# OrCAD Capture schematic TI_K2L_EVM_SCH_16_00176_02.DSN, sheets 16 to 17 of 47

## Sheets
16 PAGE18 : K2L_SOC-AMC-4: size C; title: K2L LVDS SigMux, Clock Mux, K2L Reset, K2L CML Serdes JESD/AIL,
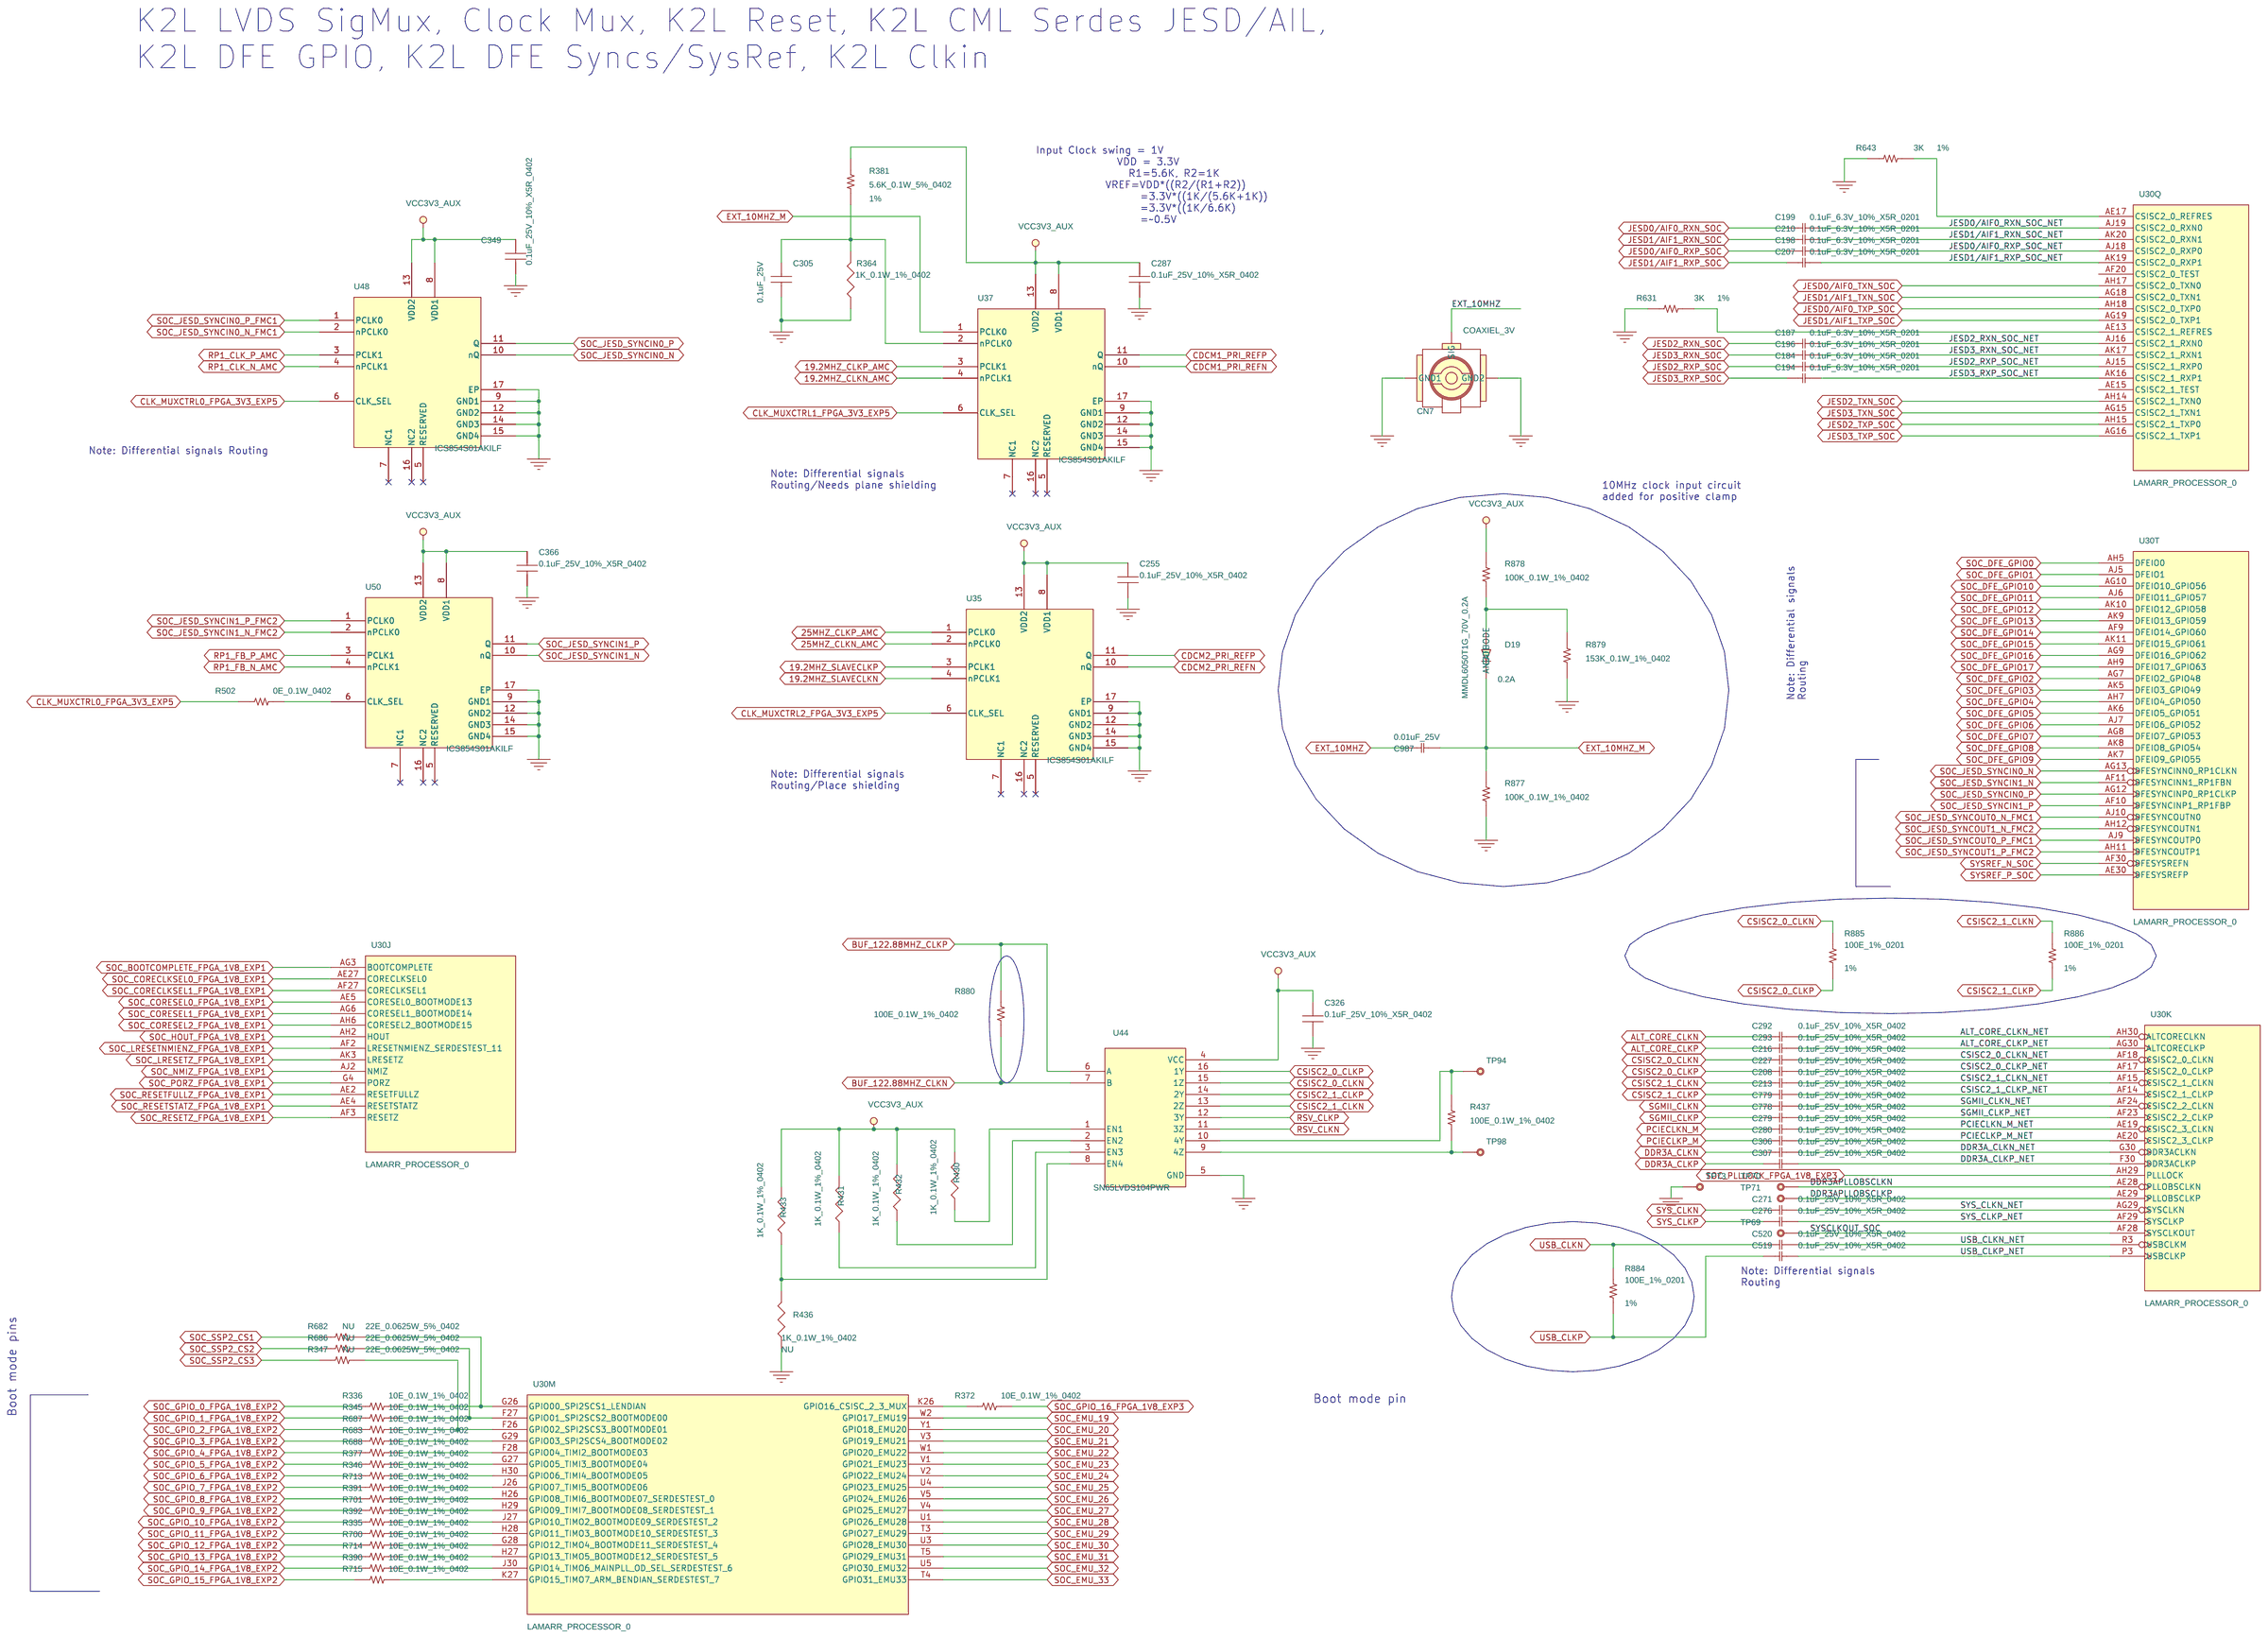
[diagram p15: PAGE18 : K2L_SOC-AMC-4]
17 PAGE47 : REVISION HISTORY: size C; title: REVISION HISTORY
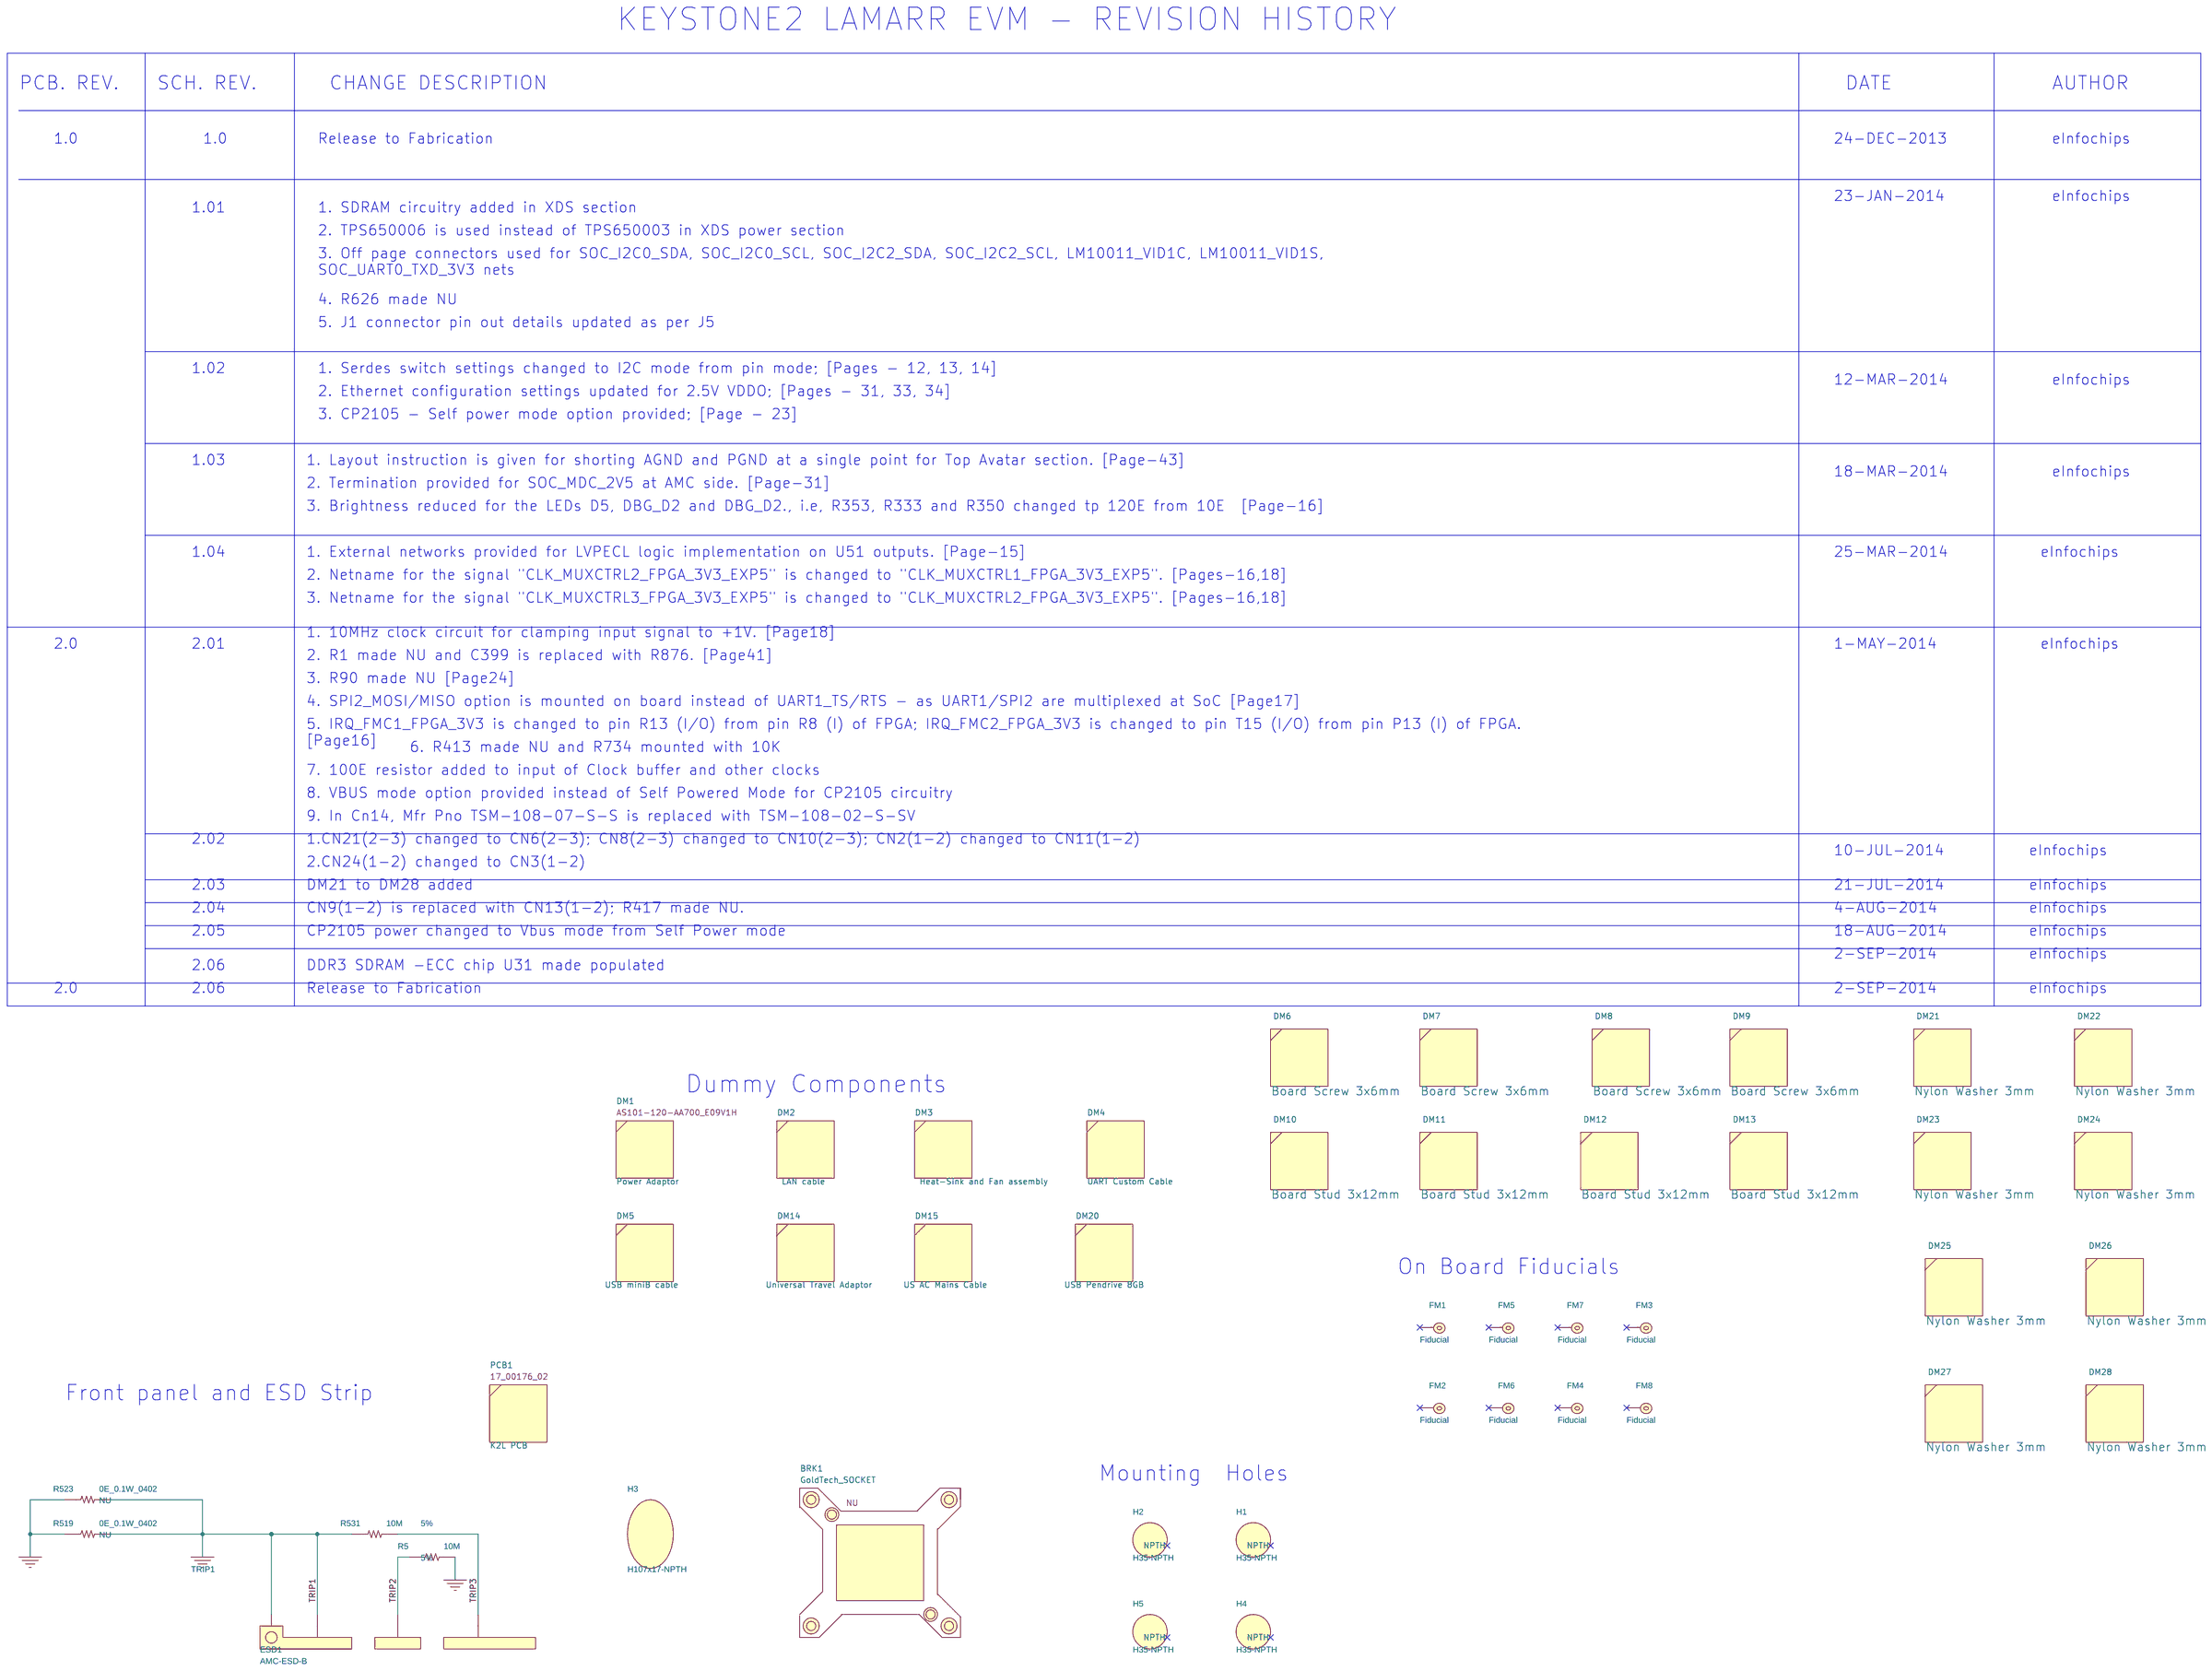
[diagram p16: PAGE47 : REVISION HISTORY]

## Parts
sheet PAGE18 : K2L_SOC-AMC-4
C184  0.1uF_6.3V_10%_X5R_0201  [CC0201]
C187  0.1uF_6.3V_10%_X5R_0201  [CC0201]
C194  0.1uF_6.3V_10%_X5R_0201  [CC0201]
C196  0.1uF_6.3V_10%_X5R_0201  [CC0201]
C198  0.1uF_6.3V_10%_X5R_0201  [CC0201]
C199  0.1uF_6.3V_10%_X5R_0201  [CC0201]
C207  0.1uF_6.3V_10%_X5R_0201  [CC0201]
C208  0.1uF_25V_10%_X5R_0402  [C0402]
C210  0.1uF_6.3V_10%_X5R_0201  [CC0201]
C213  0.1uF_25V_10%_X5R_0402  [C0402]
C216  0.1uF_25V_10%_X5R_0402  [C0402]
C227  0.1uF_25V_10%_X5R_0402  [C0402]
C255  0.1uF_25V_10%_X5R_0402  [C0402]
C271  0.1uF_25V_10%_X5R_0402  [C0402]
C276  0.1uF_25V_10%_X5R_0402  [C0402]
C279  0.1uF_25V_10%_X5R_0402  [C0402]
C280  0.1uF_25V_10%_X5R_0402  [C0402]
C287  0.1uF_25V_10%_X5R_0402  [C0402]
C292  0.1uF_25V_10%_X5R_0402  [C0402]
C293  0.1uF_25V_10%_X5R_0402  [C0402]
C305  0.1uF_25V  [C0402]
C306  0.1uF_25V_10%_X5R_0402  [C0402]
C307  0.1uF_25V_10%_X5R_0402  [C0402]
C326  0.1uF_25V_10%_X5R_0402  [C0402]
C349  0.1uF_25V_10%_X5R_0402  [C0402]
C366  0.1uF_25V_10%_X5R_0402  [C0402]
C519  0.1uF_25V_10%_X5R_0402  [C0402]
C520  0.1uF_25V_10%_X5R_0402  [C0402]
C778  0.1uF_25V_10%_X5R_0402  [C0402]
C779  0.1uF_25V_10%_X5R_0402  [C0402]
C987  0.01uF_25V  [C0402]
CN7  COAXIEL_3V  [HS_UFL-R-SMT-1]
D19  MMDL6050T1G_70V_0.2A  [SOD323]
R335  10E_0.1W_1%_0402  [R0402]
R336  10E_0.1W_1%_0402  [R0402]
R345  10E_0.1W_1%_0402  [R0402]
R346  10E_0.1W_1%_0402  [R0402]
R347  22E_0.0625W_5%_0402  [R0402]
R364  1K_0.1W_1%_0402  [R0402]
R372  10E_0.1W_1%_0402  [R0402]
R377  10E_0.1W_1%_0402  [R0402]
R381  5.6K_0.1W_5%_0402  [R0402]
R390  10E_0.1W_1%_0402  [R0402]
R391  10E_0.1W_1%_0402  [R0402]
R392  10E_0.1W_1%_0402  [R0402]
R430  1K_0.1W_1%_0402  [R0402]
R431  1K_0.1W_1%_0402  [R0402]
R432  1K_0.1W_1%_0402  [R0402]
R433  1K_0.1W_1%_0402  [R0402]
R436  1K_0.1W_1%_0402  [R0402]
R437  100E_0.1W_1%_0402  [R0402]
R502  0E_0.1W_0402  [R0402]
R631  3K  [RC0201_IPC7351_EINF]
R643  3K  [RC0201_IPC7351_EINF]
R682  22E_0.0625W_5%_0402  [R0402]
R683  10E_0.1W_1%_0402  [R0402]
R686  22E_0.0625W_5%_0402  [R0402]
R687  10E_0.1W_1%_0402  [R0402]
R688  10E_0.1W_1%_0402  [R0402]
R700  10E_0.1W_1%_0402  [R0402]
R701  10E_0.1W_1%_0402  [R0402]
R713  10E_0.1W_1%_0402  [R0402]
R714  10E_0.1W_1%_0402  [R0402]
R715  10E_0.1W_1%_0402  [R0402]
R877  100K_0.1W_1%_0402  [R0402]
R878  100K_0.1W_1%_0402  [R0402]
R879  153K_0.1W_1%_0402  [R0402]
R880  100E_0.1W_1%_0402  [R0402]
R884  100E_1%_0201  [RC0201_IPC7351_EINF]
R885  100E_1%_0201  [RC0201_IPC7351_EINF]
R886  100E_1%_0201  [RC0201_IPC7351_EINF]
TP69  TP  [TP-S40]
TP70  TP  [TP-S40]
TP71  TP  [TP-S40]
TP73  TP  [TP-S40]
TP94  TP  [TP-S40]
TP98  TP  [TP-S40]
U35  ICS854S01AKILF  [VFQFN50P300X300X100-17N_EINF]
U37  ICS854S01AKILF  [VFQFN50P300X300X100-17N_EINF]
U44  SN65LVDS104PWR  [TSSOP65P640_16]
U48  ICS854S01AKILF  [VFQFN50P300X300X100-17N_EINF]
U50  ICS854S01AKILF  [VFQFN50P300X300X100-17N_EINF]
sheet PAGE24 : K2L_JTAG
U30  LAMARR_PROCESSOR_0  [SKTBGA_Z3566_SS900-RHFB-BGA080]  (sections A,B,C,D,E,F,G,H,I,J,K,L,M,N,O,P,Q,R,S,T,U)
sheet PAGE47 : REVISION HISTORY
BRK1  GoldTech_SOCKET  [NA]
DM1  Power Adaptor  [NA]
DM2  LAN cable  [NA]
DM3  Heat-Sink and Fan assembly  [NA]
DM4  UART Custom Cable  [NA]
DM5  USB miniB cable  [NA]
DM6  Board Screw 3x6mm  [NA]
DM7  Board Screw 3x6mm  [NA]
DM8  Board Screw 3x6mm  [NA]
DM9  Board Screw 3x6mm  [NA]
DM10  Board Stud 3x12mm  [NA]
DM11  Board Stud 3x12mm  [NA]
DM12  Board Stud 3x12mm  [NA]
DM13  Board Stud 3x12mm  [NA]
DM14  Universal Travel Adaptor  [NA]
DM15  US AC Mains Cable  [NA]
DM20  USB Pendrive 8GB  [NA]
DM21  Nylon Washer 3mm  [NA]
DM22  Nylon Washer 3mm  [NA]
DM23  Nylon Washer 3mm  [NA]
DM24  Nylon Washer 3mm  [NA]
DM25  Nylon Washer 3mm  [NA]
DM26  Nylon Washer 3mm  [NA]
DM27  Nylon Washer 3mm  [NA]
DM28  Nylon Washer 3mm  [NA]
ESD1  AMC-ESD-B  [AMC-ESD-B]
FM1  Fiducial  [Fiducial]
FM2  Fiducial  [Fiducial]
FM3  Fiducial  [Fiducial]
FM4  Fiducial  [Fiducial]
FM5  Fiducial  [Fiducial]
FM6  Fiducial  [Fiducial]
FM7  Fiducial  [Fiducial]
FM8  Fiducial  [Fiducial]
H1  H35-NPTH  [H35-NPTH]
H2  H35-NPTH  [H35-NPTH]
H3  H107x17-NPTH  [H107x17-NPTH]
H4  H35-NPTH  [H35-NPTH]
H5  H35-NPTH  [H35-NPTH]
PCB1  K2L PCB  [NA]
R5  10M  [R1206]
R519  0E_0.1W_0402  [R0402]
R523  0E_0.1W_0402  [R0402]
R531  10M  [R1206]

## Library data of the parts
C184 C187 C194 C196 C198 C199 C207 C210 = 11_C_12: CAP CER 0.1UF 6.3V 10% X5R 0201; Alt Mfg: Taiyo Yuden; Alt Mfg Part#: TMK105BJ104KV-F; Characteristic: <Characteristic>; Distributor_name: DIGIKEY; Distributor_part_number: 445-1796-1-ND; EIC Part#: 03_00583_01; Manufacture: TDK Corporation; Manufacture Part Number: C0603X5R0J104K030BC; Manufacture(English): TDK Corporation; Manufacture_Part_Number: C0603X5R0J104K030BC; Manufacturer: TDK Corporation; Manufacturer_Part_No: C0603X5R0J104K030BC; Mfg: TDK Corporation; Mfg Part#: 03_00583_01; Mfr_name: TDK Corporation; Mfr_part_number: C0603X5R0J104K030BC; Oper. Temp. Range: -55°C ~ 85°C; Package: 0201; Price @ 1: 0.10000; Price @ 10K: 0.00675; Price @ 1K: 0.00810; ProcessType: SMT; RoHS: Yes; Tolerance: 10%; Vendor: DIGIKEY; Vendor Part#: 445-1796-2-ND; Vendor_Part_No: 445-1796-1-ND; Voltage: 6.3V; eI Part#: 03_00583_01
C208 C213 C216 C227 C271 C276 C279 C280 C292 C293 C306 C307 C519 C520 C778 C779 = 11_C_0: CAP CER 0.1UF 25V 10% X5R 0402; Distributor_name: DIGIKEY; Distributor_part_number: 445-4964-1-ND; EIC Part#: 03_00470_02; Manufacture: TDK Corporation; Manufacture Part Number: C1005X5R1E104K050BC; Manufacture(English): TDK Corporation; Manufacture_Part_Number: GRM155R71C104KA88D; Manufacturer: TDK Corporation; Manufacturer_Part_No: C1005X5R1E104K050BC; Mfg: Murata Electronics North America; Mfg Part#: 03_00470_02; Mfr_name: TDK Corporation; Mfr_part_number: C1005X5R1E104K050BC; Package: 0402; Price @ 1: 0.10000; Price @ 1K: 0.00420; ProcessType: SMT; Tolerance: 10%; Vendor: DIGIKEY; Vendor Part#: 445-4964-1-ND; Vendor_Part_No: 445-4964-1-ND; eI Part#: 03_00470_02
C255 C287 C305 C326 C349 C366 = CAP: CAP CER 0.1UF 25V 10% X5R 0402; Distributor_name: DIGIKEY; Distributor_part_number: 445-4964-1-ND; EIC Part#: 03_00470_02; Manufacture: TDK Corporation; Manufacture Part Number: C1005X5R1E104K050BC; Manufacture(English): TDK Corporation; Manufacture_Part_Number: GRM155R61E104KA87D; Manufacturer: TDK Corporation; Manufacturer_Part_No: C1005X5R1E104K050BC; Mfg: Murata Electronics North America; Mfg Part#: 03_00470_02; Mfr_name: TDK Corporation; Mfr_part_number: C1005X5R1E104K050BC; Price @ 1: 0.10000; Price @ 1K: 0.00960; RoHS Compliant?: RoHS Compliant; Vendor: DIGIKEY; Vendor Part#: 445-4964-1-ND; Vendor_Part_No: 445-4964-1-ND; eI Part#: 03_00470_02
C987 = 11_C_0: CAP CER 10000PF 25V 10% X7R 0402; Alt Mfg: Murata; Alt Mfg Part#: GRM155R71C103KA01D; Distributor_name: DIGIKEY; Distributor_part_number: 445-1260-1-ND; EIC Part#: 03_00029_04; Manufacture: TDK Corporation; Manufacture Part Number: C1005X7R1E103K; Manufacture(English): TDK Corporation; Manufacture_Part_Number: C1005X7R1E103K; Manufacturer: TDK Corporation; Manufacturer_Part_No: C1005X7R1E103K; Mfg: TDK Corporation; Mfg Part#: 03_00029_04; Mfr_name: TDK Corporation; Mfr_part_number: C1005X7R1E103K; Oper. Temp. Range: -55C to 125C; Package: 0402; Price @ 1: 0.10000; Price @ 10K: 0.00420; Price @ 1K: 0.00600; ProcessType: SMT; RoHS: Yes; Tolerance: 10%; Vendor: DIGIKEY; Vendor Part#: PCC103BQCT-ND; Vendor_Part_No: 445-1260-1-ND; Voltage: 16V; eI Part#: 03_00029_04
CN7 = 1654_HS_UFL-R-SMT-1_0: CONN UMC JACK STR 50 OHM SMD; Advansus_Part_Number: 12GA1654002618; Distributor_name: DIGIKEY; Distributor_part_number: H11891CT-ND; EIC Part#: TBD; Manufacture: Hirose Electric Co Ltd; Manufacture Part Number: U.FL-R-SMT-1(10); Manufacture(English): Hirose Electric Co Ltd; Manufacture_Part_Number: U.FL-R-SMT-1(10); Manufacturer: Hirose Electric Co Ltd; Manufacturer_Part_No: U.FL-R-SMT-1(10); Mfg: Hirose Electric Co Ltd; Mfg Part#: TBD; Mfr_name: Hirose Electric Co Ltd; Mfr_part_number: U.FL-R-SMT-1(10); Package: COAXIEL3P; Part_Number: 1654002618; Price @ 1: 1.67000; Price @ 10K: 0.58000; Price @ 1K: 0.70400; ProcessType: SMT; Vendor: DIGIKEY; Vendor_Part_No: H11891CT-ND; eI Part#: TBD
D19 = 130_SCHOTTKY_0805_3: DIODE SWITCHING 70V 0.2A SOD323; Characteristic: 0.2A; Distributor_name: DIGIKEY; Distributor_part_number: MMDL6050T1GOSCT-ND; EIC Part#: TBD; Manufacture: ON Semiconductor; Manufacture Part Number: MMDL6050T1G; Manufacture(English): ON Semiconductor; Manufacture_Part_Number: MMDL6050T1G; Manufacturer: ON Semiconductor; Manufacturer_Part_No: MMDL6050T1G; Mfg: ON Semiconductor; Mfg Part#: MMDL6050T1G; Mfr_name: ON Semiconductor; Mfr_part_number: MMDL6050T1G; Part_Number: MMDL6050T1G; ProcessType: SMT; Vendor: DIGIKEY; Vendor_Part_No: MMDL6050T1GOSCT-ND; eI Part#: TBD
R335 R346 R372 R377 R391 R392 R713 = 10_R_0: RES 10.0 OHM 1/10W 1% 0402 SMD; Characteristic: 5%; Distributor_name: DIGIKEY; Distributor_part_number: P10.0LCT-ND; EIC Part#: 02_00348_01; Manufacture: Panasonic - ECG; Manufacture Part Number: ERJ-2RKF10R0X; Manufacture(English): Panasonic - ECG; Manufacture_Part_Number: ERJ-2RKF10R0X; Manufacturer: Panasonic - ECG; Manufacturer_Part_No: ERJ-2RKF10R0X; Mfg: Panasonic Electronic Components; Mfg Part#: 02_00348_01; Mfr_name: Panasonic - ECG; Mfr_part_number: ERJ-2RKF10R0X; Oper. Temp. Range: -55C to 125C; Package: 0402; Price @ 1: 0.10000; Price @ 10K: 0.00347; Price @ 1K: 0.00672; ProcessType: SMT; RoHS: Yes; Tolerance: 1%; Vendor: DIGIKEY; Vendor Part#: P10.0LCT-ND; Vendor_Part_No: P10.0LCT-ND; eI Part#: 02_00266_01
R336 R714 = 10_R_0: RES 10.0 OHM 1/10W 1% 0402 SMD; Characteristic: 5%; Distributor_name: DIGIKEY; Distributor_part_number: P10.0LCT-ND; EIC Part#: 02_00348_01; Manufacture: Panasonic - ECG; Manufacture Part Number: ERJ-2RKF10R0X; Manufacture(English): Panasonic - ECG; Manufacture_Part_Number: ERJ-2RKF10R0X; Manufacturer: Panasonic - ECG; Manufacturer_Part_No: ERJ-2RKF10R0X; Mfg: Panasonic Electronic Components; Mfg Part#: 02_00348_01; Mfr_name: Panasonic - ECG; Mfr_part_number: ERJ-2RKF10R0X; Oper. Temp. Range: -55C to 125C; Package: 0402; Price @ 1: 0.10000; Price @ 10K: 0.00347; Price @ 1K: 0.00672; ProcessType: SMT; RoHS: Yes; Tolerance: 1%; Vendor: DIGIKEY; Vendor Part#: P10.0LCT-ND; Vendor_Part_No: P10.0LCT-ND; eI Part#: 02_00027_01
R345 = 10_R_0: RES 10.0 OHM 1/10W 1% 0402 SMD; Characteristic: 5%; Distributor_name: DIGIKEY; Distributor_part_number: P10.0LCT-ND; EIC Part#: 02_00348_01; Manufacture: Panasonic - ECG; Manufacture Part Number: ERJ-2RKF10R0X; Manufacture(English): Panasonic - ECG; Manufacture_Part_Number: ERJ-2RKF10R0X; Manufacturer: Panasonic - ECG; Manufacturer_Part_No: ERJ-2RKF10R0X; Mfg: Panasonic Electronic Components; Mfg Part#: 02_00348_01; Mfr_name: Panasonic - ECG; Mfr_part_number: ERJ-2RKF10R0X; Oper. Temp. Range: -55C to 125C; Package: 0402; Price @ 1: 0.10000; Price @ 10K: 0.00347; Price @ 1K: 0.00672; ProcessType: SMT; RoHS: Yes; Tolerance: 1%; Vendor: DIGIKEY; Vendor Part#: P10.0LCT-ND; Vendor_Part_No: P10.0LCT-ND; eI Part#: 02_00234_02
R347 R682 R686 = 10_R_0: RES 22 OHM 1/16W 1% 0402 SMD; Characteristic: 5%; Distributor_name: DIGIKEY; Distributor_part_number: P22JCT-ND; EIC Part#: 02_00233_01; MOUNTED: <MOUNTED>; Manufacture: Panasonic - ECG; Manufacture Part Number: ERJ-2GEJ220X; Manufacture(English): Panasonic - ECG; Manufacture_Part_Number: ERJ-2GEJ220X; Manufacturer: Panasonic - ECG; Manufacturer_Part_No: ERJ-2GEJ220X; Mfg: Panasonic - ECG; Mfg Part#: ERJ-2GEJ220X; Mfr_name: Panasonic - ECG; Mfr_part_number: ERJ-2GEJ220X; Mounting Status: NU; Mounting_Status: NU; Package: 0402; Part_Number: 105A722064; Price @ 1: 0.10000; Price @ 10K: 0.00132; Price @ 1K: 0.00233; ProcessType: SMT; Tolerance: 5%; Vendor: DIGIKEY; Vendor Part#: P22JCT-ND; Vendor_Part_No: P22JCT-ND; eI Part#: 02_00233_01
R364 = DISC_RESISTOR: RES 1.00K OHM 1/10W 1% 0402 SMD; Distributor_name: DIGIKEY; Distributor_part_number: P1.00KLCT-ND; EIC Part#: 02_00045_01; Manufacture: Panasonic - ECG; Manufacture Part Number: ERJ-2RKF1001X; Manufacture(English): Panasonic - ECG; Manufacture_Part_Number: ERJ-2RKF1001X; Manufacturer: Panasonic - ECG; Manufacturer_Part_No: ERJ-2RKF1001X; Mfg Part#: 02_00045_01; Mfr_name: Panasonic - ECG; Mfr_part_number: ERJ-2RKF1001X; Operating Temp (Degree Celsius): -55 to 85; Price @ 1: 0.10000; Price @ 10K: 0.00347; Price @ 1K: 0.00672; RoHS Compliant?: RoHS Compliant; Vendor: DIGIKEY; Vendor_Part_No: P1.00KLCT-ND; eI Part#: 02_00045_01
R381 = 10_R_0: RES 5.6K OHM 1/10W 5% 0402 SMD; AVL_Part: AVL; Advansus_Part_Number: 10G212560114030; Avalue_Part_Number: E1050505620H; Characteristic: 1%; Distributor_name: DIGIKEY; Distributor_part_number: P5.6KJTR-ND; EIC Part#: 02_00169_01; Manufacture: Panasonic - ECG; Manufacture Part Number: ERJ-2GEJ562X; Manufacture(English): Panasonic - ECG; Manufacture_Part_Number: ERJ-2GEJ562X; Manufacturer: Panasonic - ECG; Manufacturer_Part_No: ERJ-2GEJ562X; Mfg: Panasonic Electronic Components; Mfg Part#: ERJ-2GEJ562X; Mfr_name: Panasonic - ECG; Mfr_part_number: ERJ-2GEJ562X; Package: 0402; Part_Number: 105A55601A-03; Price @ 1: 0.10000; Price @ 10K: 0.00347; Price @ 1K: 0.00672; ProcessType: SMT; Tolerance: 5%; Vendor: DIGIKEY; Vendor_Part_No: P5.6KJTR-ND; eI Part#: 02_00169_01
R390 R700 R715 = 10_R_0: RES 10.0 OHM 1/10W 1% 0402 SMD; Characteristic: 5%; Distributor_name: DIGIKEY; Distributor_part_number: P10.0LCT-ND; EIC Part#: 02_00348_01; Manufacture: Panasonic - ECG; Manufacture Part Number: ERJ-2RKF10R0X; Manufacture(English): Panasonic - ECG; Manufacture_Part_Number: ERJ-2RKF10R0X; Manufacturer: Panasonic - ECG; Manufacturer_Part_No: ERJ-2RKF10R0X; Mfg: Panasonic Electronic Components; Mfg Part#: 02_00348_01; Mfr_name: Panasonic - ECG; Mfr_part_number: ERJ-2RKF10R0X; Oper. Temp. Range: -55C to 125C; Package: 0402; Price @ 1: 0.10000; Price @ 10K: 0.00347; Price @ 1K: 0.00672; ProcessType: SMT; RoHS: Yes; Tolerance: 1%; Vendor: DIGIKEY; Vendor Part#: P10.0LCT-ND; Vendor_Part_No: P10.0LCT-ND; eI Part#: 02_00019_01
R430-R433 = RESISTOR: RES 1.00K OHM 1/10W 1% 0402 SMD; Distributor_name: DIGIKEY; Distributor_part_number: P1.00KLCT-ND; EI Part#: 02_00045_01; EIC Part#: 02_00045_01; Manufacture: Panasonic - ECG; Manufacture Part Number: ERJ-2RKF1001X; Manufacture(English): Panasonic - ECG; Manufacture_Part_Number: ERJ-2RKF1001X; Manufacturer: Panasonic - ECG; Manufacturer_Part_No: ERJ-2RKF1001X; Mfg Part#: 02_00045_01; Mfr_name: Panasonic - ECG; Mfr_part_number: ERJ-2RKF1001X; Operating Temp (Degree Celsius): -55 to 85; Price @ 1: 0.10000; Price @ 10K: 0.00347; Price @ 1K: 0.00672; RoHS Compliant?: RoHS Compliant; Vendor: DIGIKEY; Vendor_Part_No: P1.00KLCT-ND
R436 = RESISTOR: RES 1.00K OHM 1/10W 1% 0402 SMD; Distributor_name: DIGIKEY; Distributor_part_number: P1.00KLCT-ND; EI Part#: 02_00045_01; EIC Part#: 02_00045_01; Manufacture: Panasonic - ECG; Manufacture Part Number: ERJ-2RKF1001X; Manufacture(English): Panasonic - ECG; Manufacture_Part_Number: ERJ-2RKF1001X; Manufacturer: Panasonic - ECG; Manufacturer_Part_No: ERJ-2RKF1001X; Mfg Part#: 02_00045_01; Mfr_name: Panasonic - ECG; Mfr_part_number: ERJ-2RKF1001X; Mounting Status: NU; Mounting_Status: NU; Operating Temp (Degree Celsius): -55 to 85; Price @ 1: 0.10000; Price @ 10K: 0.00347; Price @ 1K: 0.00672; RoHS Compliant?: RoHS Compliant; Vendor: DIGIKEY; Vendor_Part_No: P1.00KLCT-ND
R437 R880 = 10_R_0: RES 100 OHM 1/10W 1% 0402 SMD; Characteristic: 1%; Distributor_name: DIGIKEY; Distributor_part_number: P100LCT-ND; EIC Part#: 02_00043_02; Manufacture: Panasonic - ECG; Manufacture Part Number: ERJ-2RKF1000X; Manufacture(English): Panasonic - ECG; Manufacture_Part_Number: ERJ-2RKF1000X; Manufacturer: Panasonic - ECG; Manufacturer_Part_No: ERJ-2RKF1000X; Mfg: Panasonic Electronic Components; Mfg Part#: 02_00043_02; Mfr_name: Panasonic - ECG; Mfr_part_number: ERJ-2RKF1000X; Package: 0402; Part_Number: 105A510004; Price @ 1: 0.10000; Price @ 10K: 0.00347; Price @ 1K: 0.00672; ProcessType: SMT; Tolerance: 1%; Vendor: DIGIKEY; Vendor_Part_No: P100LCT-ND; eI Part#: 02_00019_01
R502 = 10_R_0: RES 0.0 OHM 1/10W JUMP 0402 SMD; Characteristic: 5%; Distributor_name: DIGIKEY; Distributor_part_number: P0.0JCT-ND; EIC Part#: 02_00019_01; Manufacture: Panasonic - ECG; Manufacture Part Number: ERJ-2GE0R00X; Manufacture(English): Panasonic - ECG; Manufacture_Part_Number: ERJ-2GE0R00X; Manufacturer: Panasonic - ECG; Manufacturer_Part_No: ERJ-2GE0R00X; Mfg: Panasonic Electronic Components; Mfg Part#: 02_00019_01; Mfr_name: Panasonic - ECG; Mfr_part_number: ERJ-2GE0R00X; Package: 0402; Part_Number: 105A700004; Price @ 1: 0.05000; Price @ 10K: 0.00248; Price @ 1K: 0.00480; ProcessType: SMT; Tolerance: 5%; Vendor: DIGIKEY; Vendor_Part_No: P0.0JCT-ND; eI Part#: 02_00019_01
R631 R643 = 10_R_0: RES 3K OHM 1/20W 5% 0201 SMD; Characteristic: 1%; Distributor_name: DIGIKEY; EIC Part#: 02_00960_01; Manufacture: Panasonic - ECG; Manufacture Part Number: ERJ-1GEJ302C; Manufacture(English): Panasonic - ECG; Manufacture_Part_Number: ERJ-1GEJ302C; Manufacturer: Panasonic - ECG; Manufacturer_Part_No: ERJ-1GEJ302C; Mfg: Panasonic - ECG; Mfg Part#: ERJ-1GEJ302C; Mfr_name: Panasonic - ECG; Mfr_part_number: ERJ-1GEJ302C; Package: 0201; ProcessType: SMT; RoHS: Yes; Tolerance: 5%; Vendor: Digikey; Vendor Part#: P3.0KAGCT-ND; Vendor_Part_No: P3.0KAGCT-ND; eI Part#: 02_00960_01
R683 = 10_R_0: RES 10.0 OHM 1/10W 1% 0402 SMD; Characteristic: 5%; Distributor_name: DIGIKEY; Distributor_part_number: P10.0LCT-ND; EIC Part#: 02_00348_01; Manufacture: Panasonic - ECG; Manufacture Part Number: ERJ-2RKF10R0X; Manufacture(English): Panasonic - ECG; Manufacture_Part_Number: ERJ-2RKF10R0X; Manufacturer: Panasonic - ECG; Manufacturer_Part_No: ERJ-2RKF10R0X; Mfg: Panasonic Electronic Components; Mfg Part#: 02_00348_01; Mfr_name: Panasonic - ECG; Mfr_part_number: ERJ-2RKF10R0X; Oper. Temp. Range: -55C to 125C; Package: 0402; Price @ 1: 0.10000; Price @ 10K: 0.00347; Price @ 1K: 0.00672; ProcessType: SMT; RoHS: Yes; Tolerance: 1%; Vendor: DIGIKEY; Vendor Part#: P10.0LCT-ND; Vendor_Part_No: P10.0LCT-ND; eI Part#: 02_00388_01
R687 R688 = 10_R_0: RES 10.0 OHM 1/10W 1% 0402 SMD; Characteristic: 5%; Distributor_name: DIGIKEY; Distributor_part_number: P10.0LCT-ND; EIC Part#: 02_00348_01; Manufacture: Panasonic - ECG; Manufacture Part Number: ERJ-2RKF10R0X; Manufacture(English): Panasonic - ECG; Manufacture_Part_Number: ERJ-2RKF10R0X; Manufacturer: Panasonic - ECG; Manufacturer_Part_No: ERJ-2RKF10R0X; Mfg: Panasonic Electronic Components; Mfg Part#: 02_00348_01; Mfr_name: Panasonic - ECG; Mfr_part_number: ERJ-2RKF10R0X; Oper. Temp. Range: -55C to 125C; Package: 0402; Price @ 1: 0.10000; Price @ 10K: 0.00347; Price @ 1K: 0.00672; ProcessType: SMT; RoHS: Yes; Tolerance: 1%; Vendor: DIGIKEY; Vendor Part#: P10.0LCT-ND; Vendor_Part_No: P10.0LCT-ND; eI Part#: 02_00348_01
R701 = 10_R_0: RES 10.0 OHM 1/10W 1% 0402 SMD; Characteristic: 5%; Distributor_name: DIGIKEY; Distributor_part_number: P10.0LCT-ND; EIC Part#: 02_00348_01; Manufacture: Panasonic - ECG; Manufacture Part Number: ERJ-2RKF10R0X; Manufacture(English): Panasonic - ECG; Manufacture_Part_Number: ERJ-2RKF10R0X; Manufacturer: Panasonic - ECG; Manufacturer_Part_No: ERJ-2RKF10R0X; Mfg: Panasonic Electronic Components; Mfg Part#: 02_00348_01; Mfr_name: Panasonic - ECG; Mfr_part_number: ERJ-2RKF10R0X; Oper. Temp. Range: -55C to 125C; Package: 0402; Price @ 1: 0.10000; Price @ 10K: 0.00347; Price @ 1K: 0.00672; ProcessType: SMT; RoHS: Yes; Tolerance: 1%; Vendor: DIGIKEY; Vendor Part#: P10.0LCT-ND; Vendor_Part_No: P10.0LCT-ND; eI Part#: 02_00018_05
R877 R878 = 10_R_0: RES 100K OHM 1/10W 1% 0402 SMD; Alt Mfg: Yageo; Alt Mfg Part#: RC0402FR-07100KL; Distributor_name: DIGIKEY; Distributor_part_number: P100KLCT-ND; EIC Part#: 02_00262_01; Manufacture: Panasonic - ECG; Manufacture Part Number: ERJ-2RKF1003X; Manufacture(English): Panasonic - ECG; Manufacture_Part_Number: ERJ-2RKF1003X; Manufacturer: Panasonic - ECG; Manufacturer_Part_No: ERJ-2RKF1003X; Mfg Part#: 02_00262_01; Mfr_name: Panasonic - ECG; Mfr_part_number: ERJ-2RKF1003X; Oper. Temp. Range: ±100ppm/°C; Package: 0402; ProcessType: SMT; RoHS: Yes; Tolerance: 1%; Vendor: DIGIKEY; Vendor Part#: P100KLCT-ND; Vendor_Part_No: P100KLCT-ND; eI Part#: 02_00027_01
R879 = 10_R_0: RES 153K OHM 1/10W 1% 0402 SMD; Distributor_name: DIGIKEY; Distributor_part_number: P154KLCT-ND; EIC Part#: TBD; Manufacture: Panasonic - ECG; Manufacture Part Number: ERJ-2RKF1543X; Manufacture(English): Panasonic - ECG; Manufacture_Part_Number: ERJ-2RKF1543X; Manufacturer: Panasonic - ECG; Manufacturer_Part_No: ERJ-2RKF1543X; Mfg Part#: ERJ-2RKF1543X; Mfr_name: Panasonic - ECG; Mfr_part_number: ERJ-2RKF1543X; Oper. Temp. Range: ±100ppm/°C; Package: 0402; ProcessType: SMT; RoHS: Yes; Tolerance: 1%; Vendor: DIGIKEY; Vendor Part#: P154KLCT-ND; Vendor_Part_No: P154KLCT-ND; eI Part#: TBD
R884-R886 = 10_R_0: RES 100 OHM 1/20W 1% 0201 SMD; Characteristic: 1%; Distributor_name: DIGIKEY; EIC Part#: 02_00043_02; Manufacture: Panasonic - ECG; Manufacture Part Number: ERJ-1GEF1000C; Manufacture(English): Panasonic - ECG; Manufacture_Part_Number: ERJ-1GEF1000C; Manufacturer: Panasonic - ECG; Manufacturer_Part_No: ERJ-1GEF1000C; Mfg: Panasonic - ECG; Mfg Part#: ERJ-1GEF1000C; Mfr_name: Panasonic - ECG; Mfr_part_number: ERJ-1GEF1000C; Package: 0201; ProcessType: SMT; RoHS: Yes; Tolerance: 1%; Vendor: Digikey; Vendor Part#: P100ABCT-ND; Vendor_Part_No: P100ABCT-ND; eI Part#: 02_00043_02
TP69-TP71 TP73 TP94 TP98 = 00_TP28_0: TEST PAD TP; Advansus_Part_Number: 0030000003; Avalue_Part_Number: 0030000003; Distributor_name: NA; Distributor_part_number: NA; EIC Part#: NA; Manufacture: NA; Manufacture Part Number: NA; Manufacture(English): NA; Manufacture_Part_Number: NA; Manufacturer: NA; Manufacturer_Part_No: NA; Mfg: NA; Mfg Part#: NA; Mfr_name: NA; Mfr_part_number: NA; Part_Number: 0030000003; Price @ 1: NA; Price @ 10K: NA; Price @ 1K: NA; ProcessType: SMT; Vendor: NA; Vendor_Part_No: NA; eI Part#: NA
U35 = ICS854S01I_1: IC CLK MULTPX 2:1 2.5GHZ 16VFQFN; Distributor_name: DIGIKEY; Distributor_part_number: 800-2561-ND; EIC Part#: TBD; Manufacture: IDT; Manufacture(English): IDT; Manufacturer: IDT; Mfg: IDT; Mfg Part#: TBD; Mfr_name: IDT; Price @ 1: 12.25000; Price @ 10K: 6.02516; Price @ 1K: 6.61298; Vendor: DIGIKEY; Vendor_Part_No: 800-2561-ND; eI Part#: 08_00006_01
U37 = ICS854S01I_1: IC CLK MULTPX 2:1 2.5GHZ 16VFQFN; Distributor_name: DIGIKEY; Distributor_part_number: 800-2561-ND; EIC Part#: TBD; Manufacture: IDT; Manufacture(English): IDT; Manufacturer: IDT; Mfg: IDT; Mfg Part#: TBD; Mfr_name: IDT; Price @ 1: 12.25000; Price @ 10K: 6.02516; Price @ 1K: 6.61298; Vendor: DIGIKEY; Vendor_Part_No: 800-2561-ND; eI Part#: 08_00090_01
U44 = IC_BUF_SN65LVDS104PWR: IC 1:4 LVDS CLOCK BUFFER 16TSSOP; Distributor_name: DIGIKEY; Distributor_part_number: 296-26359-1-ND; EIC Part#: TBD; Manufacture: TI; Manufacture(English): TI; Manufacturer: TI; Mfg: TI; Mfg Part#: TBD; Mfr_name: TI; Price @ 1: 4.46000; Price @ 10K: 2.06150; Price @ 1K: 2.23200; Vendor: DIGIKEY; Vendor_Part_No: 296-26359-1-ND; eI Part#: 08_00137_01
U48 = ICS854S01I_1: IC CLK MULTPX 2:1 2.5GHZ 16VFQFN; Distributor_name: DIGIKEY; Distributor_part_number: 800-2561-ND; EIC Part#: TBD; Manufacture: IDT; Manufacture(English): IDT; Manufacturer: IDT; Mfg: IDT; Mfg Part#: TBD; Mfr_name: IDT; Price @ 1: 12.25000; Price @ 10K: 6.02516; Price @ 1K: 6.61298; Vendor: DIGIKEY; Vendor_Part_No: 800-2561-ND; eI Part#: TBD
U50 = ICS854S01I_1: IC CLK MULTPX 2:1 2.5GHZ 16VFQFN; Distributor_name: DIGIKEY; Distributor_part_number: 800-2561-ND; EIC Part#: TBD; Manufacture: IDT; Manufacture(English): IDT; Manufacturer: IDT; Mfg: IDT; Mfg Part#: TBD; Mfr_name: IDT; Price @ 1: 12.25000; Price @ 10K: 6.02516; Price @ 1K: 6.61298; Vendor: DIGIKEY; Vendor_Part_No: 800-2561-ND; eI Part#: 01_01138_01
U30 = LAMARR_PROCESSOR_7: LAMARR-SoC 900BGA 4DSP + 2ARM; Color: Default; Distributor_name: TBD; Distributor_part_number: TBD; EIC Part#: TBD; Location X-Coordinate: 0; Location Y-Coordinate: 0; Manufacture: TI; Manufacture Part Number: TCI6630K2L; Manufacture(English): TI; Manufacture_Part_Number: TCI6630K2L; Manufacturer: TI; Manufacturer_Part_No: TCI6630K2L; Mfg: TI; Mfg Part#: TBD; Mfr_name: TI; Mfr_part_number: LAMARR-SoC; Price @ 1: TBD; Price @ 10K: TBD; Price @ 1K: TBD; Primitive: DEFAULT; SPLIT_INST: TRUE; SWAP_INFO: (S1+S2+S3+S4+S5+S6+S7+S8+S9+S10+S11+S12+S13+S14+S15+S16+S17+S18+S19+S20+S21); Vendor: TBD; Vendor_Part_No: TBD; eI Part#: TBD
BRK1 = 00_SOCKET841_CSBGA841: DSP SOCKET 800P; Distributor_name: Goldtech; Distributor_part_number: TBD; EIC Part#: TBD; Manufacture: Goldtech; Manufacture Part Number: SS900-RHFB-BGA080; Manufacture(English): Goldtech; Manufacture_Part_Number: SS900-RHFB-BGA080; Manufacturer: Goldtech; Manufacturer_Part_No: SS900-RHFB-BGA080; Mfg: Goldtech; Mfg Part#: TBD; Mfr_name: Goldtech; Mfr_part_number: SS900-RHFB-BGA080; Mounting Status: NU; Mounting_Status: NU; ProcessType: DIP; RoHS: Yes; Vendor: Goldtech; Vendor Part#: SS900-RHFB-BGA080; Vendor_Part_No: TBD; eI Part#: TBD
DM1 = DUMMY_0: Adapter 12V @0.7A, 84W Center Positive, ID 2.5mm OD 5.5mm with AC power cable pno #115-0100120-00; Distributor_name: Kingwall Electrinocs Limited; Distributor_part_number: AS101-120-AA700_E09V1H; EIC Part#: 14_00024_01; Manufacture: Kingwall Electrinocs Limited; Manufacture Part Number: AS101-120-AA700_E09V1H; Manufacture(English): Kingwall Electrinocs Limited; Manufacture_Part_Number: AS101-120-AA700_E09V1H; Manufacturer: Kingwall Electrinocs Limited; Manufacturer_Part_No: AS101-120-AA700_E09V1H; Mfg: Kingwall Electrinocs Limited; Mfg Part#: AS101-120-AA700_E09V1H; Mfr_name: Kingwall Electrinocs Limited; Mfr_part_number: AS101-120-AA700_E09V1H; Price @ 1: TBD; Price @ 10K: TBD; Price @ 1K: TBD; RoHS: Yes; Specifications: Adapter 12V @0.7A, 84W Center Positive, ID 2.5mm OD 5.5mm with AC power cable pno #115-0100120-00; Vendor: Kingwall Electrinocs Limited; Vendor Part#: AS101-120-AA700_E09V1H; Vendor_Part_No: AS101-120-AA700_E09V1H; eI Part#: 14_00024_01
DM2 = DUMMY_0: Cable Ethernet - CAT6, ~ 2 meter length; Distributor_name: Li Fa Shun; Distributor_part_number: 11180012; EIC Part#: 10_00007_01; Manufacture: Li Fa Shun; Manufacture Part Number: 11180012; Manufacture(English): Li Fa Shun; Manufacture_Part_Number: 11180012; Manufacturer: Li Fa Shun; Manufacturer_Part_No: 11180012; Mfg: Li Fa Shun; Mfg Part#: 11180012; Mfr_name: Li Fa Shun; Mfr_part_number: 11180012; RoHS: Yes; Specifications: Cable Ethernet - CAT6, ~ 2 meter length; Vendor: Li Fa Shun; Vendor Part#: 11180012; Vendor_Part_No: 11180012; eI Part#: 10_00007_01
DM3 = DUMMY_0: Heat-Sink, FAN custom design; Distributor_name: CHIA CHERNE; Distributor_part_number: K2_cooler_1004; EIC Part#: 19_00438_01; Manufacture: CHIA CHERNE; Manufacture Part Number: JAC3252A; Manufacture(English): CHIA CHERNE; Manufacture_Part_Number: JAC3252A; Manufacturer: CHIA CHERNE; Manufacturer_Part_No: JAC3252A; Mfg: CHIA CHERNE; Mfg Part#: JAC3252A; Mfr_name: CHIA CHERNE; Mfr_part_number: JAC3252A; RoHS: Yes; Specifications: Heat-Sink, FAN custom design; Vendor: CHIA CHERNE; Vendor Part#: K2_cooler_1004; Vendor_Part_No: K2_cooler_1004; eI Part#: 19_00438_01
DM4 = DUMMY_0: UART 4-Pin to DCE-9 Pin Cable; Distributor_name: Li Fa Shun; EIC Part#: TBD; Manufacture: Li Fa Shun; Manufacture Part Number: TBD; Manufacture(English): Li Fa Shun; Manufacture_Part_Number: -- NA --; Manufacturer: Li Fa Shun; Manufacturer_Part_No: TBD; Mfg: Li Fa Shun; Mfg Part#: TBD; Mfr_name: Li Fa Shun; Mfr_part_number: TBD; RoHS: Yes; Specifications: UART 4-Pin to DCE-9 Pin Cable; Vendor: TBD; Vendor Part#: -- NA --; Vendor_Part_No: TBD; eI Part#: TBD
DM5 = DUMMY_0: Cable USB Type A to Mini B, ~ 1 meter length; Distributor_name: Li Fa Shun; Distributor_part_number: TBD; EIC Part#: TBD; Manufacture: Li Fa Shun; Manufacture Part Number: TBD; Manufacture(English): Li Fa Shun; Manufacture_Part_Number: -- NA --; Manufacturer: Li Fa Shun; Manufacturer_Part_No: TBD; Mfg: Li Fa Shun; Mfg Part#: TBD; Mfr_name: Li Fa Shun; Mfr_part_number: TBD; RoHS: Yes; Specifications: Cable USB Type A to Mini B, ~ 1 meter length; Vendor: Li Fa Shun; Vendor Part#: -- NA --; Vendor_Part_No: TBD; eI Part#: TBD
DM6-DM9 = DUMMY_0: Screw 3mm, Length 6mm, Head 5.2mm; Distributor_name: TBD; Distributor_part_number: TBD; EIC Part#: 19_00134_01; Manufacture: TBD; Manufacture Part Number: TBD; Manufacture(English): TBD; Manufacture_Part_Number: -- NA --; Manufacturer: TBD; Manufacturer_Part_No: TBD; Mfg Part#: TBD; Mfr_name: TBD; Mfr_part_number: TBD; Package: -- NA --; RoHS: Yes; Specifications: Screw 3mm, Length 6mm; Vendor: TBD; Vendor Part#: -- NA --; Vendor_Part_No: TBD; eI Part#: 19_00134_01
DM10-DM13 = DUMMY_0: Stud 3mm i.d. x12mm Height; Distributor_name: TBD; Distributor_part_number: TBD; EIC Part#: 19_00137_01; Manufacture: TBD; Manufacture Part Number: TBD; Manufacture(English): TBD; Manufacture_Part_Number: -- NA --; Manufacturer: TBD; Manufacturer_Part_No: TBD; Mfg Part#: TBD; Mfr_name: TBD; Mfr_part_number: TBD; Package: -- NA --; RoHS: Yes; Specifications: Stud  3mm i.d. x12mm Height; Vendor: TBD; Vendor Part#: -- NA --; Vendor_Part_No: TBD; eI Part#: 19_00137_01
DM14 = DUMMY_0: Universal Travel Adaptor, 250V/10A 75 x 50 x 40 mm; Distributor_name: Jinggoal Int; Distributor_part_number: JC261; EIC Part#: 14_00002_01; Manufacture: Jinggoal Int; Manufacture Part Number: JC261; Manufacture(English): Jinggoal Int; Manufacture_Part_Number: JC261; Manufacturer: Jinggoal Int; Manufacturer_Part_No: JC261; Mfg: Jinggoal Int; Mfg Part#: 14_00002_01; Mfr_name: Jinggoal Int; Mfr_part_number: JC261; RoHS: Yes; Vendor: TBD; Vendor Part#: JC261; Vendor_Part_No: TBD; eI Part#: 14_00002_01
DM15 = DUMMY_0: US Style AC Mains Cable, Match with Power Brick Adapter; Distributor_name: TBD; Distributor_part_number: TBD; EIC Part#: TBD; Manufacture: TBD; Manufacture Part Number: TBD; Manufacture(English): TBD; Manufacturer: TBD; Manufacturer_Part_No: TBD; Mfg: TBD; Mfg Part#: TBD; Mfr_name: TBD; Mfr_part_number: TBD; RoHS: Yes; Vendor: TBD; Vendor_Part_No: TBD; eI Part#: TBD
DM20 = DUMMY_0: Distributor_name: TBD; Distributor_part_number: TBD; EIC Part#: TBD; Manufacture: TBD; Manufacture Part Number: TBD; Manufacture(English): TBD; Manufacturer: TBD; Manufacturer_Part_No: TBD; Mfg: TBD; Mfg Part#: TBD; Mfr_name: TBD; Mfr_part_number: TBD; RoHS: Yes; Vendor: TBD; Vendor_Part_No: TBD; eI Part#: TBD
DM21-DM28 = DUMMY_0: Screw Washer 3mm, Nylon Plastic; Distributor_name: TBD; Distributor_part_number: TBD; EIC Part#: 19_00498_01; Manufacture: TBD; Manufacture Part Number: TBD; Manufacture(English): TBD; Manufacture_Part_Number: -- NA --; Manufacturer: TBD; Manufacturer_Part_No: TBD; Mfg Part#: TBD; Mfr_name: TBD; Mfr_part_number: TBD; Package: -- NA --; RoHS: Yes; Specifications: Washer 3mm, Nylon Plastic; Vendor: TBD; Vendor Part#: -- NA --; Vendor_Part_No: TBD; eI Part#: 19_00498_01
ESD1 = AMC-ESD-B_0: ESD FOR AMC; Advansus_Part_Number: 0080000001; Avalue_Part_Number: 0080000001; Distributor_name: TBD; Distributor_part_number: TBD; EIC Part#: TBD; Manufacture: TBD; Manufacture Part Number: TBD; Manufacture(English): TBD; Manufacture_Part_Number: TBD; Manufacturer: TBD; Manufacturer_Part_No: TBD; Mfg: TBD; Mfg Part#: TBD; Mfr_name: TBD; Mfr_part_number: TBD; Part_Number: 0080000001; ProcessType: SMT; Vendor: TBD; Vendor Part#: TBD; Vendor_Part_No: TBD; eI Part#: TBD
FM1-FM8 = 00_Fiducial_0: Fiducial Mark; Distributor_name: NA; Distributor_part_number: NA; EIC Part#: NA; Manufacture: NA; Manufacture Part Number: NA; Manufacture(English): NA; Manufacture_Part_Number: NA; Manufacturer: NA; Manufacturer_Part_No: NA; Mfg: NA; Mfg Part#: NA; Mfr_name: NA; Mfr_part_number: NA; ProcessType: SMT; RoHS: Yes; Vendor: NA; Vendor Part#: NA; Vendor_Part_No: NA; eI Part#: NA
H1 H2 H4 H5 = 00_SCREWHOLE_CIRCLE_NPTH_1: SCREW HOLE  C3.5 D3.5 NPTH; Advansus Part Number: 0020200013; Avalue Part Number: 0020200013; Distributor_name: NA; Distributor_part_number: NA; EIC Part#: NA; Manufacture: NA; Manufacture Part Number: NA; Manufacture(English): NA; Manufacture_Part_Number: 20200013; Manufacturer: NA; Manufacturer_Part_No: NA; Mfg: NA; Mfg Part#: NA; Mfr_name: NA; Mfr_part_number: NA; Part Number: 0020200013; Price @ 1: NA; Price @ 10K: NA; Price @ 1K: NA; ProcessType: SMT; Vendor: NA; Vendor_Part_No: NA; eI Part#: NA
H3 = 00_SCREWHOLE_OVAL_NPTH_0: SCREW HOLE  OB10.7x1.7 D10.7x1.7 NPTH; Advansus_Part_Number: 0020200022; Avalue_Part_Number: 0020200022; Part_Number: 0020200022; ProcessType: SMT
PCB1 = DUMMY_0: K2L PCB 12 Layers 1.6mm; Distributor_name: TBD; Distributor_part_number: TBD; EIC Part#: TBD; Manufacture: TBD; Manufacture Part Number: 17_00176_02; Manufacture(English): TBD; Manufacture_Part_Number: 17_00176_02; Manufacturer: TBD; Manufacturer_Part_No: 17_00176_02; Mfg: TBD; Mfg Part#: 17_00176_02; Mfr_name: TBD; Mfr_part_number: 17_00176_02; Price @ 1: TBD; Price @ 10K: TBD; Price @ 1K: TBD; RoHS: Yes; Specifications: K2L PCB 12 Layers 1.6mm; Vendor: TBD; Vendor Part#: TBD; Vendor_Part_No: TBD; eI Part#: TBD
R5 R531 = 10_R_0: RES 10M OHM 1/4W 5% 1206 SMD; Characteristic: 5%; Distributor_name: DIGIKEY; Distributor_part_number: P10MECT-ND; EIC Part#: 02_00741_01; Manufacture: Panasonic - ECG; Manufacture Part Number: ERJ-8GEYJ106V; Manufacture(English): Panasonic - ECG; Manufacture_Part_Number: ERJ-8GEYJ106V; Manufacturer: Panasonic - ECG; Manufacturer_Part_No: ERJ-8GEYJ106V; Mfg: Panasonic - ECG; Mfg Part#: ERJ-8GEYJ106V; Mfr_name: Panasonic - ECG; Mfr_part_number: ERJ-8GEYJ106V; Package: 1206; Part_Number: 1050710052; ProcessType: SMT; RoHS: Yes; Tolerance: 5%; Vendor: DigiKey; Vendor Part#: P10MECT-ND; Vendor_Part_No: P10MECT-ND; eI Part#: 02_00741_01
R519 R523 = 10_R_0: RES 0.0 OHM 1/10W JUMP 0402 SMD; Distributor_name: DIGIKEY; Distributor_part_number: P0.0JCT-ND; EIC Part#: 02_00019_01; Manufacture: Panasonic - ECG; Manufacture Part Number: ERJ-2GE0R00X; Manufacture(English): Panasonic - ECG; Manufacture_Part_Number: ERJ-2GE0R00X; Manufacturer: Panasonic - ECG; Manufacturer_Part_No: ERJ-2GE0R00X; Mfg: PANASONIC ELECTRONIC COMPONENTS (VA); Mfg Part#: 02_00019_01; Mfr_name: Panasonic - ECG; Mfr_part_number: ERJ-2GE0R00X; Mounting Status: NU; Mounting_Status: NU; Price @ 1: 0.05000; Price @ 10K: 0.00248; Price @ 1K: 0.00480; Vendor: DIGIKEY; Vendor_Part_No: P0.0JCT-ND; eI Part#: 02_00019_01

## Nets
GND: C255.2 C287.2 C305.2 C326.2 C349.2 C366.2 CN7.1(GND1) CN7.3(GND2) R5.2 R364.1 R436.2 R519.1 R523.1 R631.1 R643.1 R877.2 R879.2 TP73.1 U35.9(GND1) U35.12(GND2) U35.14(GND3) U35.15(GND4) U35.17(EP) U37.9(GND1) U37.12(GND2) U37.14(GND3) U37.15(GND4) U37.17(EP) U44.5(GND) U48.9(GND1) U48.12(GND2) U48.14(GND3) U48.15(GND4) U48.17(EP) U50.9(GND1) U50.12(GND2) U50.14(GND3) U50.15(GND4) U50.17(EP) ; also on sheet 1 2 3 4 5 6 8 10 11 12 13 14 15 18 19 20 21 22 24 25 26 27 28 29 33 34 35 36 37 40 41 42 43 45 46 47
VCC3V3_AUX: C255.1 C287.1 C326.1 C349.1 C366.1 R381.1 R430.1 R431.1 R432.1 R433.1 R878.1 U35.8(VDD1) U35.13(VDD2) U37.8(VDD1) U37.13(VDD2) U44.4(VCC) U48.8(VDD1) U48.13(VDD2) U50.8(VDD1) U50.13(VDD2) ; also on sheet 2 4 6 8 11 12 13 18 19 22 25 26 27 28 29 33 35 37 40 45 47
19.2MHZ_CLKN_AMC: U37.4(nPCLK1) ; also on sheet 18
19.2MHZ_CLKP_AMC: U37.3(PCLK1) ; also on sheet 18
19.2MHZ_SLAVECLKN: U35.4(nPCLK1) ; also on sheet 11
19.2MHZ_SLAVECLKP: U35.3(PCLK1) ; also on sheet 11
25MHZ_CLKN_AMC: U35.2(nPCLK0) ; also on sheet 18
25MHZ_CLKP_AMC: U35.1(PCLK0) ; also on sheet 18
ALT_CORE_CLKN: C292.1 ; also on sheet 13
ALT_CORE_CLKN_NET: C292.2 U30.AH30(ALTCORECLKN)
ALT_CORE_CLKP: C293.1 ; also on sheet 13
ALT_CORE_CLKP_NET: C293.2 U30.AG30(ALTCORECLKP)
BUF_122.88MHZ_CLKN: R880.2 U44.7(B) ; also on sheet 11
BUF_122.88MHZ_CLKP: R880.1 U44.6(A) ; also on sheet 11
CDCM1_PRI_REFN: U37.10(nQ) ; also on sheet 11
CDCM1_PRI_REFP: U37.11(Q) ; also on sheet 11
CDCM2_PRI_REFN: U35.10(nQ) ; also on sheet 13
CDCM2_PRI_REFP: U35.11(Q) ; also on sheet 13
CLK_MUXCTRL0_FPGA_3V3_EXP5: R502.1 U48.6(CLK_SEL) ; also on sheet 27
CLK_MUXCTRL1_FPGA_3V3_EXP5: U37.6(CLK_SEL) ; also on sheet 27
CLK_MUXCTRL2_FPGA_3V3_EXP5: U35.6(CLK_SEL) ; also on sheet 27
CSISC2_0_CLKN: C216.1 R885.2 U44.15(1Z)
CSISC2_0_CLKN_NET: C216.2 U30.AF18(CSISC2_0_CLKN)
CSISC2_0_CLKP: C227.1 R885.1 U44.16(1Y)
CSISC2_0_CLKP_NET: C227.2 U30.AF17(CSISC2_0_CLKP)
CSISC2_1_CLKN: C208.1 R886.2 U44.13(2Z)
CSISC2_1_CLKN_NET: C208.2 U30.AF15(CSISC2_1_CLKN)
CSISC2_1_CLKP: C213.1 R886.1 U44.14(2Y)
CSISC2_1_CLKP_NET: C213.2 U30.AF14(CSISC2_1_CLKP)
DDR3A_CLKN: C306.1 ; also on sheet 13
DDR3A_CLKN_NET: C306.2 U30.G30(DDR3ACLKN)
DDR3A_CLKP: C307.1 ; also on sheet 13
DDR3A_CLKP_NET: C307.2 U30.F30(DDR3ACLKP)
DDR3APLLOBSCLKN: TP70.1 U30.AE28(PLLOBSCLKN)
DDR3APLLOBSCLKP: TP71.1 U30.AE29(PLLOBSCLKP)
EXT_10MHZ: C987.1 CN7.2(SIG)
EXT_10MHZ_M: C987.2 D19.1(CATHODE) R877.1 U37.1(PCLK0)
JESD0/AIF0_RXN_SOC: C199.1 ; also on sheet 45
JESD0/AIF0_RXN_SOC_NET: C199.2 U30.AJ19(CSISC2_0_RXN0)
JESD0/AIF0_RXP_SOC: C198.1 ; also on sheet 45
JESD0/AIF0_RXP_SOC_NET: C198.2 U30.AJ18(CSISC2_0_RXP0)
JESD0/AIF0_TXN_SOC: U30.AH17(CSISC2_0_TXN0) ; also on sheet 45
JESD0/AIF0_TXP_SOC: U30.AH18(CSISC2_0_TXP0) ; also on sheet 45
JESD1/AIF1_RXN_SOC: C210.1 ; also on sheet 45
JESD1/AIF1_RXN_SOC_NET: C210.2 U30.AK20(CSISC2_0_RXN1)
JESD1/AIF1_RXP_SOC: C207.1 ; also on sheet 45
JESD1/AIF1_RXP_SOC_NET: C207.2 U30.AK19(CSISC2_0_RXP1)
JESD1/AIF1_TXN_SOC: U30.AG18(CSISC2_0_TXN1) ; also on sheet 45
JESD1/AIF1_TXP_SOC: U30.AG19(CSISC2_0_TXP1) ; also on sheet 45
JESD2_RXN_SOC: C187.1 ; also on sheet 47
JESD2_RXN_SOC_NET: C187.2 U30.AJ16(CSISC2_1_RXN0)
JESD2_RXP_SOC: C184.1 ; also on sheet 47
JESD2_RXP_SOC_NET: C184.2 U30.AJ15(CSISC2_1_RXP0)
JESD2_TXN_SOC: U30.AH14(CSISC2_1_TXN0) ; also on sheet 47
JESD2_TXP_SOC: U30.AH15(CSISC2_1_TXP0) ; also on sheet 47
JESD3_RXN_SOC: C196.1 ; also on sheet 47
JESD3_RXN_SOC_NET: C196.2 U30.AK17(CSISC2_1_RXN1)
JESD3_RXP_SOC: C194.1 ; also on sheet 47
JESD3_RXP_SOC_NET: C194.2 U30.AK16(CSISC2_1_RXP1)
JESD3_TXN_SOC: U30.AG15(CSISC2_1_TXN1) ; also on sheet 47
JESD3_TXP_SOC: U30.AG16(CSISC2_1_TXP1) ; also on sheet 47
PCIECLKN_M: C279.1 ; also on sheet 4
PCIECLKN_M_NET: C279.2 U30.AE19(CSISC2_3_CLKN)
PCIECLKP_M: C280.1 ; also on sheet 4
PCIECLKP_M_NET: C280.2 U30.AE20(CSISC2_3_CLKP)
RP1_CLK_N_AMC: U48.4(nPCLK1) ; also on sheet 18
RP1_CLK_P_AMC: U48.3(PCLK1) ; also on sheet 18
RP1_FB_N_AMC: U50.4(nPCLK1) ; also on sheet 18
RP1_FB_P_AMC: U50.3(PCLK1) ; also on sheet 18
RSV_CLKN: U44.11(3Z) ; also on sheet 26
RSV_CLKP: U44.12(3Y) ; also on sheet 26
SGMII_CLKN: C779.1 ; also on sheet 13
SGMII_CLKN_NET: C779.2 U30.AF24(CSISC2_2_CLKN)
SGMII_CLKP: C778.1 ; also on sheet 13
SGMII_CLKP_NET: C778.2 U30.AF23(CSISC2_2_CLKP)
SOC_BOOTCOMPLETE_FPGA_1V8_EXP1: U30.AG3(BOOTCOMPLETE) ; also on sheet 28
SOC_CORECLKSEL0_FPGA_1V8_EXP1: U30.AE27(CORECLKSEL0) ; also on sheet 28
SOC_CORECLKSEL1_FPGA_1V8_EXP1: U30.AF27(CORECLKSEL1) ; also on sheet 28
SOC_CORESEL0_FPGA_1V8_EXP1: U30.AE5(CORESEL0_BOOTMODE13) ; also on sheet 28
SOC_CORESEL1_FPGA_1V8_EXP1: U30.AG6(CORESEL1_BOOTMODE14) ; also on sheet 28
SOC_CORESEL2_FPGA_1V8_EXP1: U30.AH6(CORESEL2_BOOTMODE15) ; also on sheet 28
SOC_DFE_GPIO0: U30.AH5(DFEIO0) ; also on sheet 28
SOC_DFE_GPIO1: U30.AJ5(DFEIO1) ; also on sheet 28
SOC_DFE_GPIO2: U30.AG7(DFEIO2_GPIO48) ; also on sheet 28
SOC_DFE_GPIO3: U30.AK5(DFEIO3_GPIO49) ; also on sheet 28
SOC_DFE_GPIO4: U30.AH7(DFEIO4_GPIO50) ; also on sheet 28
SOC_DFE_GPIO5: U30.AK6(DFEIO5_GPIO51) ; also on sheet 28
SOC_DFE_GPIO6: U30.AJ7(DFEIO6_GPIO52) ; also on sheet 28
SOC_DFE_GPIO7: U30.AG8(DFEIO7_GPIO53) ; also on sheet 28
SOC_DFE_GPIO8: U30.AK8(DFEIO8_GPIO54) ; also on sheet 28
SOC_DFE_GPIO9: U30.AK7(DFEIO9_GPIO55) ; also on sheet 28
SOC_DFE_GPIO10: U30.AG10(DFEIO10_GPIO56) ; also on sheet 28
SOC_DFE_GPIO11: U30.AJ6(DFEIO11_GPIO57) ; also on sheet 28
SOC_DFE_GPIO12: U30.AK10(DFEIO12_GPIO58) ; also on sheet 28
SOC_DFE_GPIO13: U30.AK9(DFEIO13_GPIO59) ; also on sheet 28
SOC_DFE_GPIO14: U30.AF9(DFEIO14_GPIO60) ; also on sheet 28
SOC_DFE_GPIO15: U30.AK11(DFEIO15_GPIO61) ; also on sheet 28
SOC_DFE_GPIO16: U30.AG9(DFEIO16_GPIO62) ; also on sheet 28
SOC_DFE_GPIO17: U30.AH9(DFEIO17_GPIO63) ; also on sheet 28
SOC_EMU_19: U30.W2(GPIO17_EMU19) ; also on sheet 6
SOC_EMU_20: U30.Y1(GPIO18_EMU20) ; also on sheet 6
SOC_EMU_21: U30.V3(GPIO19_EMU21) ; also on sheet 6
SOC_EMU_22: U30.W1(GPIO20_EMU22) ; also on sheet 6
SOC_EMU_23: U30.V1(GPIO21_EMU23) ; also on sheet 6
SOC_EMU_24: U30.V2(GPIO22_EMU24) ; also on sheet 6
SOC_EMU_25: U30.U4(GPIO23_EMU25) ; also on sheet 6
SOC_EMU_26: U30.V5(GPIO24_EMU26) ; also on sheet 6
SOC_EMU_27: U30.V4(GPIO25_EMU27) ; also on sheet 6
SOC_EMU_28: U30.U1(GPIO26_EMU28) ; also on sheet 6
SOC_EMU_29: U30.T3(GPIO27_EMU29) ; also on sheet 6
SOC_EMU_30: U30.U3(GPIO28_EMU30) ; also on sheet 6
SOC_EMU_31: U30.T5(GPIO29_EMU31) ; also on sheet 6
SOC_EMU_32: U30.U5(GPIO30_EMU32) ; also on sheet 6
SOC_EMU_33: U30.T4(GPIO31_EMU33) ; also on sheet 6
SOC_GPIO_0_FPGA_1V8_EXP2: R336.1 ; also on sheet 21 28
SOC_GPIO_1_FPGA_1V8_EXP2: R345.1 ; also on sheet 21 28
SOC_GPIO_2_FPGA_1V8_EXP2: R687.1 ; also on sheet 21 28
SOC_GPIO_3_FPGA_1V8_EXP2: R683.1 ; also on sheet 21 28
SOC_GPIO_4_FPGA_1V8_EXP2: R688.1 ; also on sheet 21 28
SOC_GPIO_5_FPGA_1V8_EXP2: R377.1 ; also on sheet 21 28
SOC_GPIO_6_FPGA_1V8_EXP2: R346.1 ; also on sheet 21 28
SOC_GPIO_7_FPGA_1V8_EXP2: R713.1 ; also on sheet 6 21 28
SOC_GPIO_8_FPGA_1V8_EXP2: R391.1 ; also on sheet 21 22 28
SOC_GPIO_9_FPGA_1V8_EXP2: R701.1 ; also on sheet 21 28
SOC_GPIO_10_FPGA_1V8_EXP2: R392.1 ; also on sheet 21 28
SOC_GPIO_11_FPGA_1V8_EXP2: R335.1 ; also on sheet 21 22 28
SOC_GPIO_12_FPGA_1V8_EXP2: R700.1 ; also on sheet 21 28
SOC_GPIO_13_FPGA_1V8_EXP2: R714.1 ; also on sheet 21 28
SOC_GPIO_14_FPGA_1V8_EXP2: R390.1 ; also on sheet 21 28
SOC_GPIO_15_FPGA_1V8_EXP2: R715.1 ; also on sheet 21 28
SOC_GPIO_16_FPGA_1V8_EXP3: R372.2 ; also on sheet 21 28
SOC_HOUT_FPGA_1V8_EXP1: U30.AH2(HOUT) ; also on sheet 28
SOC_JESD_SYNCIN0_N: U30.AG13(DFESYNCINN0_RP1CLKN) U48.10(nQ)
SOC_JESD_SYNCIN0_N_FMC1: U48.2(nPCLK0) ; also on sheet 43
SOC_JESD_SYNCIN0_P: U30.AG12(DFESYNCINP0_RP1CLKP) U48.11(Q)
SOC_JESD_SYNCIN0_P_FMC1: U48.1(PCLK0) ; also on sheet 43
SOC_JESD_SYNCIN1_N: U30.AF11(DFESYNCINN1_RP1FBN) U50.10(nQ)
SOC_JESD_SYNCIN1_N_FMC2: U50.2(nPCLK0) ; also on sheet 46
SOC_JESD_SYNCIN1_P: U30.AF10(DFESYNCINP1_RP1FBP) U50.11(Q)
SOC_JESD_SYNCIN1_P_FMC2: U50.1(PCLK0) ; also on sheet 46
SOC_JESD_SYNCOUT0_N_FMC1: U30.AJ10(DFESYNCOUTN0) ; also on sheet 43
SOC_JESD_SYNCOUT0_P_FMC1: U30.AJ9(DFESYNCOUTP0) ; also on sheet 43
SOC_JESD_SYNCOUT1_N_FMC2: U30.AH12(DFESYNCOUTN1) ; also on sheet 46
SOC_JESD_SYNCOUT1_P_FMC2: U30.AH11(DFESYNCOUTP1) ; also on sheet 46
SOC_LRESETNMIENZ_FPGA_1V8_EXP1: U30.AF2(LRESETNMIENZ_SERDESTEST_11) ; also on sheet 28
SOC_LRESETZ_FPGA_1V8_EXP1: U30.AK3(LRESETZ) ; also on sheet 28
SOC_NMIZ_FPGA_1V8_EXP1: U30.AJ2(NMIZ) ; also on sheet 28
SOC_PLLLOCK_FPGA_1V8_EXP3: U30.AH29(PLLLOCK) ; also on sheet 28
SOC_PORZ_FPGA_1V8_EXP1: U30.G4(PORZ) ; also on sheet 28 29
SOC_RESETFULLZ_FPGA_1V8_EXP1: U30.AE2(RESETFULLZ) ; also on sheet 28 29
SOC_RESETSTATZ_FPGA_1V8_EXP1: U30.AE4(RESETSTATZ) ; also on sheet 28
SOC_RESETZ_FPGA_1V8_EXP1: U30.AF3(RESETZ) ; also on sheet 28 29
SOC_SSP2_CS1: R682.2 ; also on sheet 26
SOC_SSP2_CS2: R686.2 ; also on sheet 26
SOC_SSP2_CS3: R347.2 ; also on sheet 26
SYS_CLKN: C271.1 ; also on sheet 11
SYS_CLKN_NET: C271.2 U30.AG29(SYSCLKN)
SYS_CLKP: C276.1 ; also on sheet 11
SYS_CLKP_NET: C276.2 U30.AF29(SYSCLKP)
SYSCLKOUT_SOC: TP69.1 U30.AF28(SYSCLKOUT)
SYSREF_N_SOC: U30.AF30(DFESYSREFN) ; also on sheet 28
SYSREF_P_SOC: U30.AE30(DFESYSREFP) ; also on sheet 28
TRIP1: ESD1.1 ESD1.4 R519.2 R523.2 R531.1
TRIP2: ESD1.2 R5.1
TRIP3: ESD1.3 R531.2
USB_CLKN: C520.1 R884.2 ; also on sheet 13
USB_CLKN_NET: C520.2 U30.R3(USBCLKM)
USB_CLKP: C519.1 R884.1 ; also on sheet 13
USB_CLKP_NET: C519.2 U30.P3(USBCLKP)
N17989994: R336.2 R682.1 U30.G26(GPIO00_SPI2SCS1_LENDIAN)
N17990004: R345.2 R686.1 U30.F27(GPIO01_SPI2SCS2_BOOTMODE00)
N17990024: R683.2 U30.G29(GPIO03_SPI2SCS4_BOOTMODE02)
N17990034: R688.2 U30.F28(GPIO04_TIMI2_BOOTMODE03)
N17990052: R377.2 U30.G27(GPIO05_TIMI3_BOOTMODE04)
N17990054: R346.2 U30.H30(GPIO06_TIMI4_BOOTMODE05)
N17990072: R713.2 U30.J26(GPIO07_TIMI5_BOOTMODE06)
N17990074: R391.2 U30.H26(GPIO08_TIMI6_BOOTMODE07_SERDESTEST_0)
N17990084: R701.2 U30.H29(GPIO09_TIMI7_BOOTMODE08_SERDESTEST_1)
N17990102: R392.2 U30.J27(GPIO10_TIMO2_BOOTMODE09_SERDESTEST_2)
N17990104: R335.2 U30.H28(GPIO11_TIMO3_BOOTMODE10_SERDESTEST_3)
N17990114: R700.2 U30.G28(GPIO12_TIMO4_BOOTMODE11_SERDESTEST_4)
N17990124: R714.2 U30.H27(GPIO13_TIMO5_BOOTMODE12_SERDESTEST_5)
N17990134: R390.2 U30.J30(GPIO14_TIMO6_MAINPLL_OD_SEL_SERDESTEST_6)
N17990144: R715.2 U30.K27(GPIO15_TIMO7_ARM_BENDIAN_SERDESTEST_7)
N17990176: R347.1 R687.2 U30.F26(GPIO02_SPI2SCS3_BOOTMODE01)
N17990200: R372.1 U30.K26(GPIO16_CSISC_2_3_MUX)
N18157669: R433.2 R436.1 U44.8(EN4)
N18157677: R430.2 U44.1(EN1)
N18157685: R432.2 U44.2(EN2)
N18157693: R431.2 U44.3(EN3)
N19249115: R437.1 TP94.1 U44.10(4Y)
N19249122: R437.2 TP98.1 U44.9(4Z)
N19402398: R502.2 U50.6(CLK_SEL)
N19417994: C305.1 R364.2 R381.2 U37.2(nPCLK0)
N21871231: R643.2 U30.AE17(CSISC2_0_REFRES)
N21871240: R631.2 U30.AE13(CSISC2_1_REFRES)
N23097749: D19.2(ANODE) R878.2 R879.1

Not connected (* = marked no-connect by the designer): FM1 1*; FM2 1*; FM3 1*; FM4 1*; FM5 1*; FM6 1*; FM7 1*; FM8 1*; H1 1(NPTH)*; H2 1(NPTH)*; H3 1; H4 1(NPTH)*; H5 1(NPTH)*; U30 AE15(CSISC2_1_TEST) AF20(CSISC2_0_TEST); U35 5(RESERVED)* 7(NC1)* 16(NC2)*; U37 5(RESERVED)* 7(NC1)* 16(NC2)*; U48 5(RESERVED)* 7(NC1)* 16(NC2)*; U50 5(RESERVED)* 7(NC1)* 16(NC2)*

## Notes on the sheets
sheet 16
- K2L LVDS SigMux, Clock Mux, K2L Reset, K2L CML Serdes JESD/AIL,
  K2L DFE GPIO, K2L DFE Syncs/SysRef, K2L Clkin
- Input Clock swing = 1V
- VDD = 3.3V
- R1=5.6K, R2=1K
- VREF=VDD*((R2/(R1+R2))
- =3.3V*((1K/(5.6K+1K))
- =3.3V*((1K/6.6K)
- =~0.5V
- Note: Differential signals Routing
- Note: Differential signals
  Routing/Needs plane shielding
- 10MHz clock input circuit
  added for positive clamp
- Note: Differential signals
  Routing
- Note: Differential signals
  Routing/Place shielding
- Note: Differential signals
  Routing
- Boot mode pin
- Boot mode pins
sheet 17
- KEYSTONE2 LAMARR EVM - REVISION HISTORY
- PCB. REV.
- SCH. REV.
- CHANGE DESCRIPTION
- DATE
- AUTHOR
- 1.0
- 1.0
- Release to Fabrication
- 24-DEC-2013
- eInfochips
- 1.01
- 1. SDRAM circuitry added in XDS section
- 23-JAN-2014
- eInfochips
- 2. TPS650006 is used instead of TPS650003 in XDS power section
- 3. Off page connectors used for SOC_I2C0_SDA, SOC_I2C0_SCL, SOC_I2C2_SDA, SOC_I2C2_SCL, LM10011_VID1C, LM10011_VID1S,
  SOC_UART0_TXD_3V3 nets
- 4. R626 made NU
- 5. J1 connector pin out details updated as per J5
- 1.02
- 1. Serdes switch settings changed to I2C mode from pin mode; [Pages - 12, 13, 14]
- 12-MAR-2014
- eInfochips
- 2. Ethernet configuration settings updated for 2.5V VDDO; [Pages - 31, 33, 34]
- 3. CP2105 - Self power mode option provided; [Page - 23]
- 1.03
- 1. Layout instruction is given for shorting AGND and PGND at a single point for Top Avatar section. [Page-43]
- 18-MAR-2014
- eInfochips
- 2. Termination provided for SOC_MDC_2V5 at AMC side. [Page-31]
- 3. Brightness reduced for the LEDs D5, DBG_D2 and DBG_D2., i.e, R353, R333 and R350 changed tp 120E from 10E  [Page-16]
- 1.04
- 1. External networks provided for LVPECL logic implementation on U51 outputs. [Page-15]
- 25-MAR-2014
- eInfochips
- 2. Netname for the signal "CLK_MUXCTRL2_FPGA_3V3_EXP5" is changed to "CLK_MUXCTRL1_FPGA_3V3_EXP5". [Pages-16,18]
- 3. Netname for the signal "CLK_MUXCTRL3_FPGA_3V3_EXP5" is changed to "CLK_MUXCTRL2_FPGA_3V3_EXP5". [Pages-16,18]
- 1. 10MHz clock circuit for clamping input signal to +1V. [Page18]
- 2.0
- 2.01
- 2. R1 made NU and C399 is replaced with R876. [Page41]
- 1-MAY-2014
- eInfochips
- 3. R90 made NU [Page24]
- 4. SPI2_MOSI/MISO option is mounted on board instead of UART1_TS/RTS - as UART1/SPI2 are multiplexed at SoC [Page17]
- 5. IRQ_FMC1_FPGA_3V3 is changed to pin R13 (I/O) from pin R8 (I) of FPGA; IRQ_FMC2_FPGA_3V3 is changed to pin T15 (I/O) from pin P13 (I) of FPGA.
  [Page16]
- 6. R413 made NU and R734 mounted with 10K
- 7. 100E resistor added to input of Clock buffer and other clocks
- 8. VBUS mode option provided instead of Self Powered Mode for CP2105 circuitry
- 9. In Cn14, Mfr Pno TSM-108-07-S-S is replaced with TSM-108-02-S-SV
- 2.02
- 1.CN21(2-3) changed to CN6(2-3); CN8(2-3) changed to CN10(2-3); CN2(1-2) changed to CN11(1-2)
- 10-JUL-2014
- eInfochips
- 2.CN24(1-2) changed to CN3(1-2)
- 2.03
- DM21 to DM28 added
- 21-JUL-2014
- eInfochips
- 2.04
- CN9(1-2) is replaced with CN13(1-2); R417 made NU.
- 4-AUG-2014
- eInfochips
- 2.05
- CP2105 power changed to Vbus mode from Self Power mode
- 18-AUG-2014
- eInfochips
- 2.06
- DDR3 SDRAM -ECC chip U31 made populated
- 2-SEP-2014
- eInfochips
- 2.0
- 2.06
- Release to Fabrication
- 2-SEP-2014
- eInfochips
- Dummy Components
- On Board Fiducials
- Front panel and ESD Strip
- Mounting  Holes
